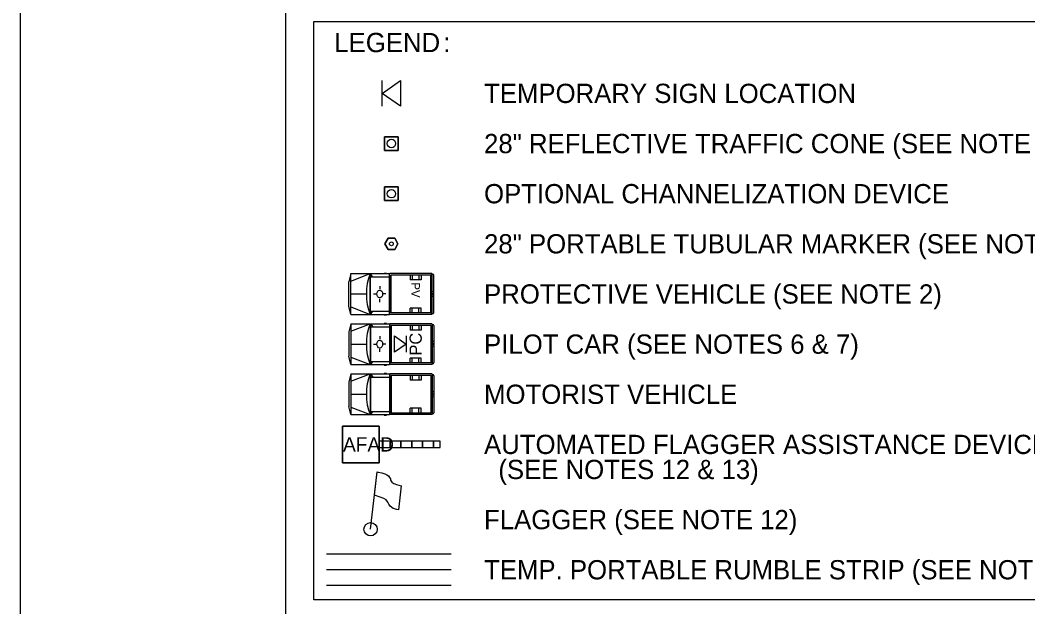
# Model space of a CAD drawing. Extents: x 99999.1 to 100095.7, y 99995 to 100010.7.
# Drawn here: x 100039.062 to 100042.622, y 100001.151 to 100003.222 of the extents above; entities that cross this region are included whole.
import ezdxf

# ---------------------------------------------------------------- set-up
doc = ezdxf.new("R2010")
doc.units = 0
for name, color, linetype in [('SH_GI_PlotLimits', 7, 'Continuous'), ('SH_GI_SheetBorder', 7, 'Continuous'), ('TR_WZ_AFAD', 7, 'Continuous'), ('TR_WZ_FlaggingStation', 7, 'Continuous'), ('TR_WZ_MotoristVehicle', 7, 'Continuous'), ('TR_WZ_PortableSignMountBlk-Org', 7, 'Continuous'), ('TR_WZ_PortableSignMountBlk-Wht', 7, 'Continuous'), ('TR_WZ_ProtectiveVehicle', 7, 'Continuous'), ('TR_WZ_TrafficCone', 7, 'Continuous'), ('TR_WZ_TubularMarker', 7, 'Continuous'), ('TR_WZ_WorkZoneDetails', 7, 'Continuous'), ('TR_WZ_WorkZoneTextCurrent', 7, 'Continuous')]:
    doc.layers.add(name, color=color, linetype=linetype)

msp = doc.modelspace()

# ---------------------------------------------------------------- linework, layer by layer
at = {"layer": 'SH_GI_PlotLimits'}
msp.add_lwpolyline([(100039.0625, 99999.6875), (100056.0625, 99999.6875), (100056.0625, 100010.6875), (100039.0625, 100010.6875)], close=True, dxfattribs=at)
at = {"layer": 'SH_GI_SheetBorder'}
msp.add_line((100040, 100010.375), (100040, 100000), dxfattribs=at)
at = {"layer": 'TR_WZ_AFAD'}
for p, q in [((100040.2009, 100001.6597), (100040.2009, 100001.7893)), ((100040.2009, 100001.7893), (100040.3305, 100001.7893)), ((100040.3305, 100001.7893), (100040.2009, 100001.7893)), ((100040.2009, 100001.7893), (100040.2009, 100001.6597)), ((100040.3305, 100001.7893), (100040.3305, 100001.6597)), ((100040.3305, 100001.7293), (100040.3305, 100001.7893)), ((100040.3689, 100001.7353), (100040.3305, 100001.7353)), ((100040.3305, 100001.7353), (100040.3305, 100001.7293)), ((100040.3305, 100001.7293), (100040.3305, 100001.7245)), ((100040.4073, 100001.7353), (100040.3689, 100001.7353)), ((100040.3689, 100001.7137), (100040.4073, 100001.7137)), ((100040.4457, 100001.7353), (100040.4073, 100001.7353)), ((100040.4073, 100001.7245), (100040.4073, 100001.7353)), ((100040.4073, 100001.7137), (100040.4073, 100001.7245)), ((100040.4073, 100001.7137), (100040.4457, 100001.7137)), ((100040.4841, 100001.7353), (100040.4457, 100001.7353)), ((100040.4457, 100001.7353), (100040.4457, 100001.7245)), ((100040.4457, 100001.7245), (100040.4457, 100001.7137)), ((100040.4457, 100001.7137), (100040.4841, 100001.7137)), ((100040.5225, 100001.7353), (100040.4841, 100001.7353)), ((100040.4841, 100001.7245), (100040.4841, 100001.7353)), ((100040.4841, 100001.7137), (100040.4841, 100001.7245)), ((100040.4841, 100001.7137), (100040.5225, 100001.7137)), ((100040.5225, 100001.7353), (100040.5225, 100001.7245)), ((100040.5225, 100001.7245), (100040.5225, 100001.7137)), ((100040.5225, 100001.7137), (100040.5465, 100001.7137)), ((100040.3305, 100001.6597), (100040.2009, 100001.6597)), ((100040.2009, 100001.6597), (100040.3305, 100001.6597))]:
    msp.add_line(p, q, dxfattribs=at)
for points in [[(100040.3305, 100001.7137), (100040.5465, 100001.7137), (100040.5465, 100001.7353), (100040.3305, 100001.7353)], [(100040.3305, 100001.6597), (100040.3305, 100001.7197), (100040.3305, 100001.7293)], [(100040.3305, 100001.7245), (100040.3305, 100001.7197), (100040.3305, 100001.7137), (100040.3689, 100001.7137)], [(100040.3689, 100001.7137), (100040.3689, 100001.7245), (100040.3689, 100001.7353)], [(100040.3689, 100001.7353), (100040.3689, 100001.7245), (100040.3689, 100001.7137)], [(100040.4073, 100001.7353), (100040.4073, 100001.7245), (100040.4073, 100001.7137)], [(100040.4457, 100001.7137), (100040.4457, 100001.7245), (100040.4457, 100001.7353)], [(100040.4841, 100001.7353), (100040.4841, 100001.7245), (100040.4841, 100001.7137)], [(100040.5225, 100001.7137), (100040.5225, 100001.7245), (100040.5225, 100001.7353)], [(100040.5465, 100001.7137), (100040.5465, 100001.7353), (100040.5225, 100001.7353)]]:
    msp.add_lwpolyline(points, dxfattribs=at)
at = {"layer": 'TR_WZ_FlaggingStation'}
for p, q in [((100040.3003, 100001.4247), (100040.3234, 100001.627)), ((100040.314, 100001.5449), (100040.3234, 100001.6272)), ((100040.4083, 100001.5784), (100040.3987, 100001.494)), ((100040.314, 100001.5449), (100040.314, 100001.5449))]:
    msp.add_line(p, q, dxfattribs=at)
for points in [[(100040.3234, 100001.6272), (100040.3275, 100001.6263), (100040.3404, 100001.6238), (100040.3503, 100001.6208), (100040.3573, 100001.6165), (100040.3634, 100001.6131), (100040.3675, 100001.6081), (100040.3706, 100001.6025), (100040.371, 100001.5981), (100040.3748, 100001.5914), (100040.3826, 100001.586), (100040.3915, 100001.5823), (100040.4083, 100001.5784)], [(100040.3987, 100001.494), (100040.3929, 100001.4951), (100040.3801, 100001.4984), (100040.3689, 100001.506), (100040.3642, 100001.5136), (100040.3614, 100001.521), (100040.3548, 100001.5288), (100040.3469, 100001.5333), (100040.3344, 100001.5384), (100040.314, 100001.5449)]]:
    msp.add_lwpolyline(points, dxfattribs=at)
msp.add_circle((100040.3003, 100001.4247), 0.0234, dxfattribs=at)
at = {"layer": 'TR_WZ_MotoristVehicle'}
for p, q in [((100040.2305, 100002.1506), (100040.2239, 100002.1215)), ((100040.2305, 100002.1506), (100040.2305, 100002.0066)), ((100040.2305, 100002.1506), (100040.3665, 100002.1506)), ((100040.2305, 100002.1242), (100040.2985, 100002.1506)), ((100040.2985, 100002.1506), (100040.2985, 100002.0066)), ((100040.2998, 100002.1506), (100040.2998, 100002.0066)), ((100040.2998, 100002.1506), (100040.3084, 100002.1394)), ((100040.2998, 100002.1394), (100040.3665, 100002.1394)), ((100040.348, 100002.1526), (100040.3562, 100002.1526)), ((100040.3665, 100002.1506), (100040.3665, 100002.0066)), ((100040.5166, 100002.1506), (100040.3685, 100002.1506)), ((100040.3685, 100002.1506), (100040.3685, 100002.0066)), ((100040.5124, 100002.1448), (100040.3727, 100002.1448)), ((100040.3727, 100002.1448), (100040.3727, 100002.0123)), ((100040.4395, 100002.1448), (100040.4395, 100002.1283)), ((100040.4467, 100002.1448), (100040.4467, 100002.1283)), ((100040.4711, 100002.1448), (100040.4711, 100002.1283)), ((100040.4791, 100002.1448), (100040.4791, 100002.1283)), ((100040.5124, 100002.1448), (100040.5124, 100002.0123)), ((100040.5166, 100002.1506), (100040.5166, 100002.0066)), ((100040.5204, 100002.1482), (100040.5171, 100002.1482)), ((100040.5171, 100002.1482), (100040.5171, 100002.0089)), ((100040.5236, 100002.1438), (100040.5236, 100002.0133)), ((100040.2239, 100002.1215), (100040.2239, 100002.0356)), ((100040.3324, 100002.1071), (100040.3324, 100002.0955)), ((100040.4791, 100002.1283), (100040.4395, 100002.1283)), ((100040.2305, 100002.0786), (100040.2852, 100002.0786)), ((100040.3107, 100002.0787), (100040.3198, 100002.0786)), ((100040.3426, 100002.0783), (100040.3426, 100002.0783)), ((100040.3546, 100002.078), (100040.3439, 100002.0783)), ((100040.5236, 100002.0887), (100040.5171, 100002.086)), ((100040.5236, 100002.0684), (100040.5171, 100002.0711)), ((100040.5218, 100002.0786), (100040.5189, 100002.0786)), ((100040.5204, 100002.0806), (100040.5204, 100002.0765)), ((100040.2305, 100002.0066), (100040.2239, 100002.0356)), ((100040.2305, 100002.0329), (100040.2985, 100002.0066)), ((100040.3329, 100002.0509), (100040.3327, 100002.0617)), ((100040.4395, 100002.0123), (100040.4395, 100002.0289)), ((100040.4791, 100002.0289), (100040.4395, 100002.0289)), ((100040.4467, 100002.0123), (100040.4467, 100002.0289)), ((100040.4711, 100002.0123), (100040.4711, 100002.0289)), ((100040.4791, 100002.0123), (100040.4791, 100002.0289)), ((100040.2305, 100002.0066), (100040.3665, 100002.0066)), ((100040.2998, 100002.0177), (100040.3665, 100002.0177)), ((100040.3069, 100002.0177), (100040.2998, 100002.0066)), ((100040.348, 100002.0045), (100040.3562, 100002.0045)), ((100040.5166, 100002.0066), (100040.3685, 100002.0066)), ((100040.5124, 100002.0123), (100040.3727, 100002.0123)), ((100040.5204, 100002.0089), (100040.5171, 100002.0089)), ((100040.2305, 100001.9735), (100040.2239, 100001.9445)), ((100040.2305, 100001.9735), (100040.2305, 100001.8295)), ((100040.2305, 100001.9735), (100040.3665, 100001.9735)), ((100040.2305, 100001.9472), (100040.2985, 100001.9735)), ((100040.2985, 100001.9735), (100040.2985, 100001.8295)), ((100040.2998, 100001.9735), (100040.2998, 100001.8295)), ((100040.2998, 100001.9735), (100040.3084, 100001.9624)), ((100040.2998, 100001.9624), (100040.3665, 100001.9624)), ((100040.348, 100001.9756), (100040.3562, 100001.9756)), ((100040.3665, 100001.9735), (100040.3665, 100001.8295)), ((100040.5166, 100001.9735), (100040.3685, 100001.9735)), ((100040.3685, 100001.9735), (100040.3685, 100001.8295)), ((100040.5124, 100001.9678), (100040.3727, 100001.9678)), ((100040.3727, 100001.9678), (100040.3727, 100001.8353)), ((100040.4395, 100001.9678), (100040.4395, 100001.9512)), ((100040.4467, 100001.9678), (100040.4467, 100001.9512)), ((100040.4711, 100001.9678), (100040.4711, 100001.9512)), ((100040.4791, 100001.9678), (100040.4791, 100001.9512)), ((100040.5124, 100001.9678), (100040.5124, 100001.8353)), ((100040.5166, 100001.9735), (100040.5166, 100001.8295)), ((100040.5204, 100001.9712), (100040.5171, 100001.9712)), ((100040.5171, 100001.9712), (100040.5171, 100001.8319)), ((100040.5236, 100001.9668), (100040.5236, 100001.8363)), ((100040.2239, 100001.9445), (100040.2239, 100001.8586)), ((100040.4791, 100001.9512), (100040.4395, 100001.9512)), ((100040.2305, 100001.9015), (100040.2852, 100001.9015)), ((100040.5236, 100001.9117), (100040.5171, 100001.909)), ((100040.5236, 100001.8914), (100040.5171, 100001.8941)), ((100040.5218, 100001.9015), (100040.5189, 100001.9015)), ((100040.5204, 100001.9036), (100040.5204, 100001.8995)), ((100040.2305, 100001.8295), (100040.2239, 100001.8586)), ((100040.2305, 100001.8559), (100040.2985, 100001.8295)), ((100040.4395, 100001.8353), (100040.4395, 100001.8518)), ((100040.4791, 100001.8518), (100040.4395, 100001.8518)), ((100040.4467, 100001.8353), (100040.4467, 100001.8518)), ((100040.4711, 100001.8353), (100040.4711, 100001.8518)), ((100040.4791, 100001.8353), (100040.4791, 100001.8518)), ((100040.2305, 100001.8295), (100040.3665, 100001.8295)), ((100040.2998, 100001.8407), (100040.3665, 100001.8407)), ((100040.3069, 100001.8407), (100040.2998, 100001.8295)), ((100040.348, 100001.8275), (100040.3562, 100001.8275)), ((100040.5166, 100001.8295), (100040.3685, 100001.8295)), ((100040.5124, 100001.8353), (100040.3727, 100001.8353)), ((100040.5204, 100001.8319), (100040.5171, 100001.8319))]:
    msp.add_line(p, q, dxfattribs=at)
for centre, major_axis, start_param, end_param in [((100040.3957, 100002.0786), (0, -0.1511), 4.215667, 5.208926), ((100040.5204, 100002.1438), (0, 0.00439), 4.712389, 6.283185), ((100040.5204, 100002.0133), (0, -0.00439), 0, 1.570796), ((100040.3957, 100001.9015), (0, -0.1511), 4.215667, 5.208926), ((100040.5204, 100001.9668), (0, 0.00439), 4.712389, 6.283185), ((100040.5204, 100001.8363), (0, -0.00439), 0, 1.570796)]:
    msp.add_ellipse(centre, major_axis=major_axis, ratio=0.73155, start_param=start_param, end_param=end_param, dxfattribs=at)
for centre, major_axis in [((100040.3324, 100002.0786), (0, 0.0139)), ((100040.5204, 100002.0786), (0, 0.00203)), ((100040.5204, 100001.9015), (0, 0.00203))]:
    msp.add_ellipse(centre, major_axis=major_axis, ratio=0.73155, dxfattribs=at)
at = {"layer": 'TR_WZ_PortableSignMountBlk-Org'}
msp.add_line((100040.3414, 100002.9188), (100040.3414, 100003.0088), dxfattribs=at)
msp.add_lwpolyline([(100040.3414, 100002.9637), (100040.406, 100003.0088), (100040.406, 100002.9188)], close=True, dxfattribs=at)
at = {"layer": 'TR_WZ_PortableSignMountBlk-Wht'}
msp.add_line((100040.4259, 100002.1073), (100040.4259, 100002.0497), dxfattribs=at)
msp.add_lwpolyline([(100040.4259, 100002.0786), (100040.3845, 100002.0497), (100040.3845, 100002.1073)], close=True, dxfattribs=at)
at = {"layer": 'TR_WZ_ProtectiveVehicle'}
for p, q in [((100040.2305, 100002.3276), (100040.2239, 100002.2985)), ((100040.2305, 100002.1836), (100040.2305, 100002.3276)), ((100040.2305, 100002.3276), (100040.3665, 100002.3276)), ((100040.2305, 100002.3012), (100040.2985, 100002.3276)), ((100040.2985, 100002.1836), (100040.2985, 100002.3276)), ((100040.2998, 100002.1836), (100040.2998, 100002.3276)), ((100040.3069, 100002.3165), (100040.2998, 100002.3276)), ((100040.2998, 100002.3165), (100040.3665, 100002.3165)), ((100040.348, 100002.3296), (100040.3562, 100002.3296)), ((100040.3665, 100002.1836), (100040.3665, 100002.3276)), ((100040.5166, 100002.3276), (100040.3685, 100002.3276)), ((100040.3685, 100002.1836), (100040.3685, 100002.3276)), ((100040.5124, 100002.3219), (100040.3727, 100002.3219)), ((100040.3727, 100002.1894), (100040.3727, 100002.3219)), ((100040.4395, 100002.3219), (100040.4395, 100002.3053)), ((100040.4467, 100002.3219), (100040.4467, 100002.3053)), ((100040.4711, 100002.3219), (100040.4711, 100002.3053)), ((100040.4791, 100002.3219), (100040.4791, 100002.3053)), ((100040.5124, 100002.1894), (100040.5124, 100002.3219)), ((100040.5166, 100002.1836), (100040.5166, 100002.3276)), ((100040.5204, 100002.3252), (100040.5171, 100002.3252)), ((100040.5171, 100002.186), (100040.5171, 100002.3252)), ((100040.5236, 100002.1904), (100040.5236, 100002.3209)), ((100040.2239, 100002.2127), (100040.2239, 100002.2985)), ((100040.3329, 100002.2833), (100040.3327, 100002.2725)), ((100040.4791, 100002.3053), (100040.4395, 100002.3053)), ((100040.2305, 100002.2556), (100040.2852, 100002.2556)), ((100040.3107, 100002.2555), (100040.3198, 100002.2556)), ((100040.3426, 100002.2559), (100040.3426, 100002.2559)), ((100040.3546, 100002.2562), (100040.3439, 100002.2559)), ((100040.5236, 100002.2658), (100040.5171, 100002.2631)), ((100040.5236, 100002.2455), (100040.5171, 100002.2482)), ((100040.5218, 100002.2556), (100040.5189, 100002.2556)), ((100040.5204, 100002.2536), (100040.5204, 100002.2576)), ((100040.2305, 100002.1836), (100040.2239, 100002.2127)), ((100040.2305, 100002.21), (100040.2985, 100002.1836)), ((100040.3324, 100002.2271), (100040.3324, 100002.2387)), ((100040.2305, 100002.1836), (100040.3665, 100002.1836)), ((100040.2998, 100002.1836), (100040.3084, 100002.1948)), ((100040.2998, 100002.1948), (100040.3665, 100002.1948)), ((100040.348, 100002.1816), (100040.3562, 100002.1816)), ((100040.5166, 100002.1836), (100040.3685, 100002.1836)), ((100040.5124, 100002.1894), (100040.3727, 100002.1894)), ((100040.4791, 100002.2059), (100040.4395, 100002.2059)), ((100040.4395, 100002.1894), (100040.4395, 100002.2059)), ((100040.4467, 100002.1894), (100040.4467, 100002.2059)), ((100040.4711, 100002.1894), (100040.4711, 100002.2059)), ((100040.4791, 100002.1894), (100040.4791, 100002.2059)), ((100040.5204, 100002.186), (100040.5171, 100002.186))]:
    msp.add_line(p, q, dxfattribs=at)
for centre, major_axis, start_param, end_param in [((100040.3957, 100002.2556), (0, -0.1511), 4.215852, 5.209111), ((100040.5204, 100002.3209), (0, 0.00439), 4.712389, 6.283185), ((100040.5204, 100002.1904), (0, -0.00439), 6.283185, 7.853982)]:
    msp.add_ellipse(centre, major_axis=major_axis, ratio=0.73155, start_param=start_param, end_param=end_param, dxfattribs=at)
for centre, major_axis in [((100040.3324, 100002.2556), (0, 0.0139)), ((100040.5204, 100002.2556), (0, 0.00203))]:
    msp.add_ellipse(centre, major_axis=major_axis, ratio=0.73155, dxfattribs=at)
at = {"layer": 'TR_WZ_TrafficCone'}
for points in [[(100040.3497, 100002.8107), (100040.3977, 100002.8107), (100040.3977, 100002.7627), (100040.3497, 100002.7627), (100040.3497, 100002.8107)], [(100040.3497, 100002.7627), (100040.3977, 100002.7627), (100040.3977, 100002.8107), (100040.3497, 100002.8107), (100040.3497, 100002.7627)], [(100040.3497, 100002.6337), (100040.3977, 100002.6337), (100040.3977, 100002.5857), (100040.3497, 100002.5857), (100040.3497, 100002.6337)], [(100040.3497, 100002.5857), (100040.3977, 100002.5857), (100040.3977, 100002.6337), (100040.3497, 100002.6337), (100040.3497, 100002.5857)]]:
    msp.add_lwpolyline(points, dxfattribs=at)
for centre in [(100040.3737, 100002.7867), (100040.3737, 100002.6097)]:
    msp.add_circle(centre, 0.015, dxfattribs=at)
at = {"layer": 'TR_WZ_TubularMarker'}
msp.add_lwpolyline([(100040.3506, 100002.4327), (100040.3622, 100002.4527), (100040.3853, 100002.4527), (100040.3968, 100002.4327), (100040.3853, 100002.4127), (100040.3622, 100002.4127)], close=True, dxfattribs=at)
msp.add_lwpolyline([(100040.3622, 100002.4127), (100040.3853, 100002.4127), (100040.3968, 100002.4327), (100040.3853, 100002.4527), (100040.3622, 100002.4527), (100040.3506, 100002.4327), (100040.3622, 100002.4127)], dxfattribs=at)
msp.add_circle((100040.3737, 100002.4327), 0.00667, dxfattribs=at)
at = {"layer": 'TR_WZ_WorkZoneDetails'}
for p, q in [((100040.585, 100001.3368), (100040.145, 100001.3368)), ((100040.585, 100001.2819), (100040.145, 100001.2819)), ((100040.585, 100001.2263), (100040.145, 100001.2263))]:
    msp.add_line(p, q, dxfattribs=at)
at = {"layer": 'TR_WZ_WorkZoneTextCurrent'}
msp.add_lwpolyline([(100040.1, 100003.2174), (100043.2886, 100003.2174), (100043.2886, 100001.1759), (100040.1, 100001.1759)], close=True, dxfattribs=at)

# ---------------------------------------------------------------- texts
at = {"layer": 'TR_WZ_AFAD'}
msp.add_text('AFAD', height=0.0504, dxfattribs=at).set_placement((100040.203, 100001.6993))
at = {"layer": 'TR_WZ_MotoristVehicle'}
msp.add_text('PC', height=0.0432, rotation=90, dxfattribs=at).set_placement((100040.4809, 100002.0382))
at = {"layer": 'TR_WZ_ProtectiveVehicle'}
msp.add_text('PV', height=0.03006, rotation=270, dxfattribs=at).set_placement((100040.4442, 100002.2964))
at = {"layer": 'TR_WZ_WorkZoneTextCurrent'}
for s, p in [('LEGEND', (100040.172, 100003.1094)), (':', (100040.5568, 100003.1094)), ('TEMPORARY SIGN LOCATION ', (100040.7009, 100002.9298)), ('28" REFLECTIVE TRAFFIC CONE (SEE NOTE 3)', (100040.7009, 100002.7527)), ('OPTIONAL CHANNELIZATION DEVICE', (100040.7009, 100002.5757)), ('28" PORTABLE TUBULAR MARKER (SEE NOTE 8)', (100040.7009, 100002.3987)), ('PROTECTIVE VEHICLE (SEE NOTE 2)', (100040.7009, 100002.2216)), ('PILOT CAR (SEE NOTES 6 & 7)', (100040.7009, 100002.0446)), ('MOTORIST VEHICLE', (100040.7009, 100001.8675)), ('AUTOMATED FLAGGER ASSISTANCE DEVICE', (100040.7009, 100001.6905)), ('  (SEE NOTES 12 & 13)', (100040.7009, 100001.602)), ('FLAGGER (SEE NOTE 12)', (100040.7009, 100001.4249)), ('TEMP. PORTABLE RUMBLE STRIP (SEE NOTE 14)', (100040.7009, 100001.2479))]:
    msp.add_text(s, height=0.068, rotation=360, dxfattribs=at).set_placement(p)

doc.saveas('drawing.dxf')
